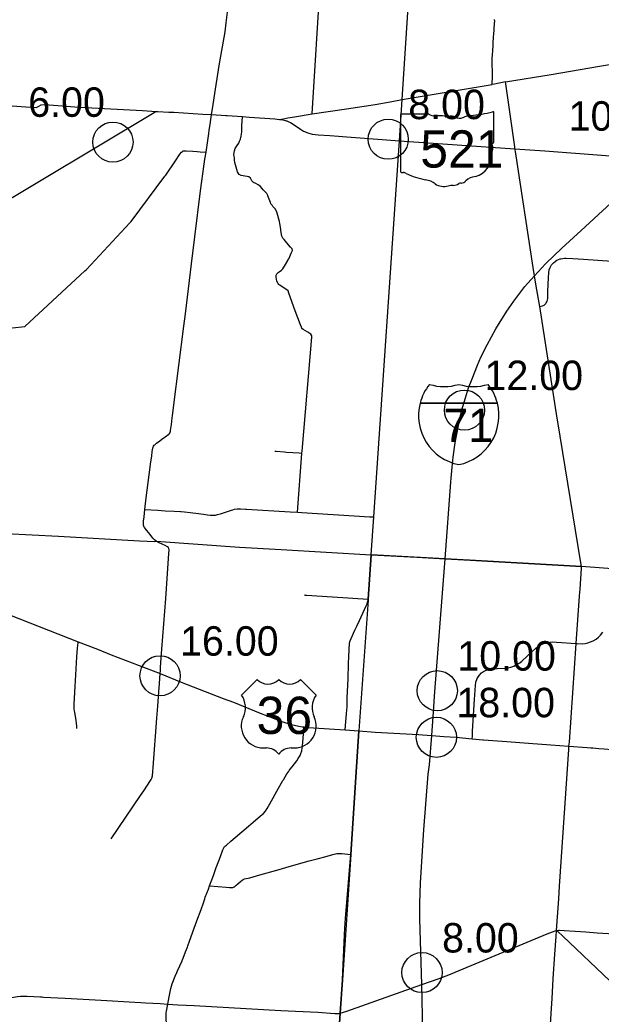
# Model space of a CAD drawing. Extents: x 1597222 to 1925846, y 496284 to 911751.
# Drawn here: x 1833850 to 1855559, y 815408 to 852560 of the extents above; entities that cross this region are included whole.
import ezdxf

# ---------------------------------------------------------------- set-up
doc = ezdxf.new("R2010")
doc.units = 0
for name, color, linetype in [('Default', 7, 'Continuous'), ('GM_X_County_Road', 7, 'Continuous'), ('GM_X_Interstate_Route', 7, 'Continuous'), ('GM_X_Interstate_Shield', 7, 'Continuous'), ('GM_X_State_Route', 7, 'Continuous'), ('GM_X_State_Shield', 7, 'Continuous'), ('GM_X_Township', 7, 'Continuous'), ('GM_X_Township_Road', 7, 'Continuous'), ('GM_X_US_Route', 7, 'Continuous'), ('GM_X_US_Shield', 7, 'Continuous')]:
    doc.layers.add(name, color=color, linetype=linetype)

msp = doc.modelspace()

# ---------------------------------------------------------------- linework, layer by layer
at = {"layer": 'Default'}
for centre in [(1837325, 847992), (1847607, 848101), (1850454, 837978), (1839084, 828052), (1849439, 827494), (1849405, 825751), (1848869, 816960)]:
    msp.add_circle(centre, 750, dxfattribs=at)
at = {"layer": 'GM_X_County_Road'}
for points in [[(1841006, 849018), (1841051, 849314), (1841101, 849645), (1841295, 850857), (1841512, 852119), (1841560, 852444), (1841625, 853051)], [(1852342, 847746), (1852332, 847819), (1852002, 850172), (1851992, 850242), (1851578, 850159), (1851485, 850140), (1851503, 850457), (1851507, 850519), (1851495, 850994), (1851492, 851085), (1851506, 851296), (1851510, 851368), (1851545, 851947), (1851548, 852007), (1851578, 852429), (1851584, 852517), (1851577, 852569)], [(1851992, 850242), (1853696, 850524), (1855503, 850836), (1856828, 851059), (1859214, 851472), (1860807, 851754), (1861908, 851967)], [(1848128, 849585), (1851485, 850140)], [(1828890, 849668), (1828890, 849668), (1828924, 849648), (1828977, 849643), (1829879, 849585), (1833037, 849389), (1834076, 849311), (1834469, 849288), (1834642, 849380), (1834781, 849392), (1836063, 849299), (1838431, 849174), (1838783, 849153), (1838998, 849141)], [(1843595, 848838), (1843637, 848852), (1843852, 848894), (1844102, 848937), (1844768, 849049), (1846050, 849232), (1847118, 849400), (1847685, 849497), (1848128, 849585)], [(1846971, 832575), (1846971, 832575), (1847065, 833986), (1848030, 848046), (1848128, 849585)], [(1838934, 833082), (1838875, 833130), (1838820, 833190), (1838713, 833324), (1838593, 833477), (1838502, 833596), (1838490, 833616), (1838481, 833634), (1838474, 833652), (1838468, 833671), (1838464, 833691), (1838461, 833711), (1838461, 833751), (1838466, 833825), (1838487, 833985), (1838519, 834265), (1838567, 834705), (1838674, 835560), (1838743, 836040), (1838773, 836253), (1838796, 836429), (1838814, 836551), (1838826, 836590), (1838844, 836629), (1838867, 836664), (1838885, 836685), (1838954, 836740), (1839072, 836824), (1839157, 836890), (1839273, 836974), (1839413, 837081), (1839426, 837095), (1839438, 837110), (1839458, 837143), (1839466, 837161), (1839472, 837179), (1839477, 837198), (1839478, 837221), (1839510, 837440), (1839538, 837684), (1839547, 837760), (1839596, 838176), (1839967, 841111), (1840035, 841581), (1840259, 843439), (1840381, 844450), (1840596, 846166), (1840736, 847171), (1840762, 847354), (1840807, 847615), (1840906, 848311), (1840922, 848444), (1840955, 848656), (1841006, 849018)], [(1833453, 841041), (1833926, 841092), (1834029, 841103), (1836280, 843180), (1836334, 843229), (1837952, 844970), (1838003, 845024), (1839263, 846719), (1839296, 846763), (1839657, 847296), (1839829, 847544), (1839890, 847618), (1839921, 847646), (1839949, 847661), (1839978, 847670), (1839994, 847672), (1840065, 847668), (1840312, 847648), (1840471, 847640), (1840580, 847631), (1840807, 847615)], [(1854821, 832136), (1854806, 832276), (1853927, 837618), (1853916, 837681), (1853270, 841855), (1853135, 842607), (1853071, 843001), (1853019, 843312), (1852359, 847640), (1852342, 847746)], [(1839405, 832831), (1839399, 832841), (1839368, 832866), (1839279, 832914), (1839055, 833020), (1838934, 833082)], [(1839090, 828131), (1839096, 828247), (1839106, 828377), (1839155, 829045), (1839297, 830940), (1839419, 832616), (1839427, 832761), (1839419, 832807), (1839405, 832831)], [(1846005, 826026), (1846043, 826645), (1846071, 826890), (1846074, 827230), (1846113, 827938), (1846126, 828505), (1846142, 828753), (1846166, 829288), (1846184, 829357), (1846219, 829446), (1846366, 829753), (1846439, 829908), (1846529, 830116), (1846779, 830659), (1846815, 830740), (1846834, 830797), (1846854, 830870), (1846863, 830918), (1846971, 832575)], [(1854753, 831025), (1854754, 831032), (1854771, 831285), (1854824, 832063), (1854821, 832136)], [(1854354, 825422), (1854377, 825574), (1854631, 829258), (1854753, 831025)], [(1850745, 825700), (1850750, 825794), (1850761, 825975), (1850834, 827165), (1850866, 827684), (1850884, 827817), (1850934, 827955), (1851000, 828061), (1851089, 828156), (1851167, 828213), (1851241, 828254), (1851342, 828291), (1851425, 828309), (1851528, 828316), (1851677, 828322), (1851998, 828336), (1852079, 828347), (1852187, 828372), (1852301, 828412), (1852366, 828442), (1852454, 828491), (1852522, 828537), (1852593, 828595), (1852985, 828961), (1853110, 829075), (1853198, 829141), (1853285, 829192), (1853384, 829239), (1853471, 829269), (1853550, 829290), (1853650, 829307), (1853759, 829315), (1853892, 829310), (1854631, 829258)], [(1837255, 821964), (1838352, 823573), (1838477, 823753), (1838734, 824138), (1838754, 824176), (1838776, 824230), (1838797, 824315), (1838813, 824478), (1838822, 824624), (1838961, 826468), (1838996, 826913), (1839038, 827452), (1839065, 827768), (1839090, 828131)], [(1844428, 825666), (1844430, 825701), (1844439, 825894), (1844455, 826141)], [(1843676, 824135), (1843691, 824163), (1843825, 824382), (1843877, 824459), (1843910, 824506), (1843948, 824557), (1844017, 824645), (1844192, 824870), (1844248, 824955), (1844313, 825075), (1844345, 825149), (1844376, 825251), (1844395, 825340), (1844404, 825395), (1844424, 825605), (1844428, 825666)], [(1853892, 818538), (1853927, 819045), (1853979, 819713), (1854011, 820193), (1854357, 825298), (1854354, 825422)], [(1840108, 817915), (1840125, 817960), (1840185, 818129), (1840360, 818619), (1840456, 818888), (1840615, 819321), (1840707, 819568), (1840763, 819722), (1840773, 819774), (1840889, 820072), (1840934, 820196), (1841077, 820583), (1841186, 820882), (1841282, 821134), (1841343, 821301), (1841435, 821553), (1841459, 821602), (1841482, 821642), (1841498, 821666), (1841562, 821727), (1841728, 821872), (1841885, 822009), (1842387, 822426), (1842567, 822583), (1842842, 822816), (1842945, 822908), (1843026, 822996), (1843091, 823097), (1843134, 823175), (1843183, 823260), (1843512, 823845), (1843676, 824135)], [(1845813, 815443), (1846057, 815523), (1847704, 816100), (1848860, 816509), (1849512, 816739), (1849867, 816870), (1850255, 817032), (1853548, 818404), (1853845, 818524), (1853892, 818538)], [(1852972, 804706), (1852981, 804856), (1853110, 806745), (1853175, 807697), (1853246, 808714), (1853530, 812876), (1853592, 813742), (1853681, 815234), (1853705, 815613), (1853731, 815995), (1853772, 816725), (1853832, 817646), (1853875, 818312), (1853892, 818538)], [(1853892, 818538), (1853963, 818545), (1854011, 818543), (1854178, 818529), (1854595, 818503), (1854991, 818481), (1855415, 818448), (1856692, 818365)], [(1857182, 815299), (1857153, 815378), (1857124, 815436), (1857089, 815491), (1857039, 815553), (1856865, 815727), (1856650, 815933), (1856316, 816250), (1855886, 816655), (1854135, 818318), (1853948, 818496), (1853892, 818538)], [(1839372, 815780), (1839425, 816059), (1839488, 816370), (1839533, 816537), (1839646, 816828), (1839707, 816968), (1839735, 817030), (1839908, 817404), (1839909, 817406), (1839949, 817498), (1840041, 817739), (1840108, 817915)], [(1831958, 816015), (1832323, 815989), (1832460, 815979), (1832837, 815953), (1832930, 815950), (1833024, 815953), (1833112, 815962), (1833413, 816008), (1833762, 816064), (1833870, 816076), (1833979, 816082), (1834125, 816080), (1834617, 816051), (1834676, 816048), (1834735, 816046), (1835535, 816000), (1836888, 815933), (1838141, 815859), (1838366, 815848), (1838544, 815828), (1839093, 815806), (1839372, 815780)], [(1842846, 805301), (1842837, 805328), (1842772, 805518), (1842519, 806229), (1841146, 810217), (1840928, 810827), (1840065, 813066), (1839518, 814468), (1839479, 814577), (1839387, 814825), (1839342, 814985), (1839324, 815084), (1839310, 815214), (1839307, 815315), (1839311, 815371), (1839312, 815408), (1839319, 815463), (1839325, 815513), (1839372, 815780)], [(1839372, 815780), (1839750, 815761), (1840057, 815746), (1840358, 815730), (1843594, 815549), (1844974, 815476), (1845607, 815434), (1845771, 815433), (1845813, 815443)]]:
    msp.add_lwpolyline(points, dxfattribs=at)
at = {"layer": 'GM_X_Interstate_Route'}
for points in [[(1853497, 843457), (1854091, 844035), (1854810, 844689), (1856408, 846161), (1857196, 846884), (1857351, 847028)], [(1852825, 842723), (1853071, 843001), (1853486, 843445), (1853497, 843457)], [(1849960, 835440), (1849991, 835852), (1850027, 836225), (1850112, 836751), (1850219, 837345), (1850270, 837606), (1850358, 837993), (1850490, 838443), (1850609, 838810), (1850743, 839153), (1850946, 839662), (1851071, 839958), (1851303, 840416), (1851627, 841020), (1852032, 841680), (1852294, 842043), (1852715, 842598), (1852825, 842723)], [(1849232, 825823), (1849312, 826884), (1849342, 827283), (1849536, 829857), (1849737, 832422), (1849949, 835289), (1849960, 835440)], [(1848894, 814749), (1848860, 816509), (1848794, 818972), (1848791, 819542), (1848815, 820309), (1848943, 822290), (1849103, 824378), (1849147, 824725), (1849232, 825823)]]:
    msp.add_lwpolyline(points, dxfattribs=at)
at = {"layer": 'GM_X_Interstate_Shield'}
for p, q in [((1848799, 838237), (1851684, 838237)), ((1851684, 838237), (1848799, 838237)), ((1851684, 838237), (1848799, 838237)), ((1848799, 838237), (1851684, 838237)), ((1851684, 838237), (1848799, 838237)), ((1851684, 838237), (1848799, 838237))]:
    msp.add_line(p, q, dxfattribs=at)
for centre, start, end in [((1850616, 837777), 141.669, 165.8066), ((1850616, 837777), 141.669, 165.8066), ((1849693, 840733), 253.0091, 286.9909), ((1849693, 840733), 253.0091, 286.9909), ((1850789, 840733), 253.0091, 286.9909), ((1850789, 840733), 253.0091, 286.9909), ((1849866, 837777), 14.1934, 38.331), ((1849866, 837777), 14.1934, 38.331), ((1850616, 837777), 165.8066, 258.463), ((1850616, 837777), 165.8066, 258.463), ((1849866, 837777), 281.537, 14.1934), ((1849866, 837777), 281.537, 14.1934)]:
    msp.add_arc(centre, 1875, start, end, dxfattribs=at)
at = {"layer": 'GM_X_State_Route'}
for points in [[(1824240, 840319), (1825270, 840939), (1826096, 841440), (1826142, 841474), (1826514, 841694), (1827976, 842576), (1829017, 843200), (1831719, 844816), (1832490, 845282), (1838868, 849097), (1838914, 849121), (1838998, 849141), (1839418, 849116)], [(1839418, 849116), (1839597, 849106), (1840678, 849037), (1841006, 849018)], [(1841006, 849018), (1841537, 848985), (1841586, 848982)], [(1841586, 848982), (1842167, 848948), (1842431, 848928)], [(1842431, 848928), (1843370, 848858), (1843543, 848843)], [(1843543, 848843), (1843595, 848838), (1843668, 848826), (1843754, 848804), (1843796, 848791), (1843824, 848782), (1843899, 848751), (1843959, 848721), (1844210, 848561), (1844336, 848473), (1844448, 848406), (1844608, 848336), (1844771, 848292), (1844988, 848267), (1845431, 848234), (1846221, 848181), (1847382, 848093), (1848030, 848046), (1852342, 847746), (1853462, 847664), (1857695, 847346)]]:
    msp.add_lwpolyline(points, dxfattribs=at)
at = {"layer": 'GM_X_State_Shield'}
for p, q in [((1848068, 849005), (1848068, 846891)), ((1848068, 849005), (1848068, 846891)), ((1849122, 849041), (1848102, 849041)), ((1849122, 849041), (1848102, 849041)), ((1851549, 847988), (1851549, 849093)), ((1851549, 847988), (1851549, 849093)), ((1851548, 847988), (1851549, 847988)), ((1851548, 847988), (1851549, 847988))]:
    msp.add_line(p, q, dxfattribs=at)
for centre, major_axis, start_param, end_param in [((1848108, 849009), (40.3, 0), 1.712693, 3.28349), ((1848108, 849009), (40.3, 0), 1.712693, 3.28349), ((1849364, 849286), (391, 0), 4.042523, 4.731795), ((1849364, 849286), (391, 0), 4.042523, 4.731795), ((1849494, 847855), (1404, 0), 1.404758, 1.657858), ((1849494, 847855), (1404, 0), 1.404758, 1.657858), ((1849813, 849020), (113, 0), 3.836095, 5.185415), ((1849813, 849020), (113, 0), 3.836095, 5.185415), ((1849978, 848776), (235, 0), 0.950623, 2.079405), ((1849978, 848776), (235, 0), 0.950623, 2.079405), ((1850281, 849111), (282, 0), 4.081561, 5.145723), ((1850281, 849111), (282, 0), 4.081561, 5.145723), ((1850780, 848395), (743, 0), 1.699011, 2.107814), ((1850780, 848395), (743, 0), 1.699011, 2.107814), ((1850309, 851922), (3691, 0), 4.814394, 5.042369), ((1850309, 851922), (3691, 0), 4.814394, 5.042369), ((1851510, 849098), (38.7, 0), 6.141152, 7.989035), ((1851510, 849098), (38.7, 0), 6.141152, 7.989035), ((1851540, 847907), (60, 0), 1.883978, 3.671073), ((1851540, 847907), (60, 0), 1.883978, 3.671073), ((1851158, 847767), (360, 0), 5.934695, 6.695948), ((1851158, 847767), (360, 0), 5.934695, 6.695948), ((1851507, 847984), (41.5, 0), 5.05454, 6.418171), ((1851507, 847984), (41.5, 0), 5.05454, 6.418171), ((1850515, 847385), (923, 0), 5.101752, 6.440018), ((1850515, 847385), (923, 0), 5.101752, 6.440018), ((1851687, 847525), (262, 0), 2.387724, 3.262537), ((1851687, 847525), (262, 0), 2.387724, 3.262537), ((1848108, 846887), (40.7, 0), 3.00124, 4.508301), ((1848108, 846887), (40.7, 0), 3.00124, 4.508301), ((1848115, 847103), (310, 0), 4.665946, 4.897461), ((1848115, 847103), (310, 0), 4.665946, 4.897461), ((1848178, 846769), (112, 0), 0.519207, 1.627899), ((1848178, 846769), (112, 0), 0.519207, 1.627899), ((1849591, 848668), (2665, 0), 4.195997, 4.488961), ((1849591, 848668), (2665, 0), 4.195997, 4.488961), ((1850905, 846298), (506, 0), 1.647645, 2.488434), ((1850905, 846298), (506, 0), 1.647645, 2.488434), ((1848797, 845942), (834, 0), 0.823519, 1.323587), ((1848797, 845942), (834, 0), 0.823519, 1.323587), ((1849699, 846759), (529, 0), 4.026481, 4.996735), ((1849699, 846759), (529, 0), 4.026481, 4.996735), ((1850004, 846028), (435, 0), 1.495662, 1.94098), ((1850004, 846028), (435, 0), 1.495662, 1.94098), ((1850043, 846601), (282, 0), 4.691044, 5.507374), ((1850043, 846601), (282, 0), 4.691044, 5.507374), ((1850298, 846396), (79.4, 0), 1.147584, 2.315152), ((1850298, 846396), (79.4, 0), 1.147584, 2.315152), ((1850264, 846686), (298, 0), 4.937069, 5.64225), ((1850264, 846686), (298, 0), 4.937069, 5.64225)]:
    msp.add_ellipse(centre, major_axis=major_axis, ratio=0.8, start_param=start_param, end_param=end_param, dxfattribs=at)
at = {"layer": 'GM_X_Township'}
for points in [[(1858606, 831851), (1854821, 832136), (1851310, 832334), (1849737, 832422), (1846971, 832575), (1847065, 833986), (1848030, 848046), (1848128, 849585), (1848752, 859146), (1850615, 859080), (1861827, 858324)], [(1832327, 833414), (1835297, 833263), (1838313, 833094), (1838887, 833066), (1838934, 833082), (1842052, 832856), (1843609, 832772), (1846971, 832575), (1846863, 830918), (1846854, 830870), (1846509, 825988), (1846205, 821378), (1845900, 816686), (1845813, 815443), (1845687, 813540)]]:
    msp.add_lwpolyline(points, dxfattribs=at)
at = {"layer": 'GM_X_Township_Road'}
for points in [[(1844768, 849049), (1845076, 854067), (1843711, 854157), (1843711, 854157)], [(1843111, 845983), (1843107, 845993), (1843076, 846068), (1843002, 846144), (1842938, 846209), (1842834, 846328), (1842792, 846377), (1842745, 846400), (1842658, 846443), (1842580, 846479), (1842518, 846549), (1842493, 846596), (1842466, 846646), (1842396, 846696), (1842344, 846704), (1842246, 846720), (1842194, 846729), (1842110, 846744), (1842034, 846776), (1842009, 846822), (1841976, 846884), (1841907, 847139), (1841882, 847229), (1841869, 847334), (1841860, 847401), (1841852, 847454), (1841840, 847528), (1841863, 847661), (1841896, 847749), (1841968, 847865), (1842022, 847959), (1842058, 848032), (1842084, 848101), (1842105, 848172), (1842112, 848208), (1842126, 848296), (1842134, 848374), (1842137, 848623), (1842150, 848766), (1842167, 848948)], [(1843823, 844224), (1843717, 844351), (1843674, 844402), (1843630, 844475), (1843602, 844684), (1843594, 844739), (1843558, 844947), (1843544, 845028), (1843460, 845334), (1843438, 845415), (1843386, 845501), (1843361, 845526), (1843349, 845538), (1843298, 845589), (1843268, 845633), (1843228, 845691), (1843209, 845741), (1843188, 845798), (1843111, 845983)], [(1843771, 843420), (1843860, 843570), (1843863, 843575), (1843892, 843625), (1843997, 843867), (1844030, 843945), (1844022, 844005), (1843954, 844068), (1843823, 844224)], [(1843677, 842566), (1843609, 842613), (1843559, 842648), (1843513, 842674), (1843503, 842690), (1843491, 842712), (1843453, 842794), (1843429, 842865), (1843423, 842949), (1843423, 843023), (1843441, 843067), (1843499, 843117), (1843540, 843150), (1843617, 843209), (1843675, 843258), (1843771, 843420)], [(1853270, 841855), (1853375, 841876), (1853430, 841904), (1853489, 841960), (1853510, 841987), (1853529, 842020), (1853540, 842047), (1853556, 842102), (1853564, 842152), (1853571, 842416), (1853597, 842931), (1853607, 843104), (1853625, 843215), (1853660, 843313), (1853709, 843404), (1853779, 843484), (1853838, 843531), (1853844, 843535)], [(1853844, 843535), (1853861, 843548), (1853911, 843579), (1853965, 843605), (1854028, 843627), (1854060, 843636), (1854125, 843648), (1854191, 843655), (1854258, 843655), (1854503, 843639), (1854896, 843613), (1855969, 843548)], [(1844215, 834160), (1844384, 836360), (1844385, 836371), (1844391, 836449), (1844748, 840708), (1844751, 840754), (1844719, 840820), (1844674, 840847), (1844607, 840886), (1844427, 840996), (1844381, 841024), (1844362, 841073), (1844329, 841160), (1844136, 841693), (1843898, 842352), (1843869, 842432), (1843677, 842566)], [(1843367, 836442), (1843417, 836439), (1843733, 836416), (1843809, 836411), (1844283, 836378), (1844385, 836371)], [(1838519, 834265), (1839003, 834239), (1839280, 834220), (1839610, 834202), (1839845, 834186), (1839872, 834185)], [(1839872, 834185), (1840004, 834176), (1840213, 834155), (1840314, 834142), (1840419, 834128), (1840709, 834086), (1840854, 834066), (1840955, 834057), (1841058, 834052), (1841152, 834058), (1841236, 834072), (1841340, 834101), (1841488, 834149), (1841639, 834205), (1841751, 834242), (1841801, 834256), (1841870, 834271), (1841962, 834284), (1842018, 834287), (1842093, 834287), (1842280, 834278)], [(1842280, 834278), (1842320, 834277), (1843950, 834176), (1844215, 834160), (1844383, 834149), (1846926, 833987), (1847065, 833986)], [(1832327, 833414), (1835297, 833263), (1838313, 833094), (1838887, 833066), (1838934, 833082)], [(1846971, 832575), (1848673, 832481)], [(1848673, 832481), (1849737, 832422), (1850671, 832370)], [(1850671, 832370), (1851310, 832334), (1854821, 832136)], [(1844480, 831093), (1844497, 831060), (1844550, 831060), (1845524, 831004), (1846863, 830918)], [(1854631, 829258), (1854661, 829256), (1854846, 829249), (1854959, 829261), (1855061, 829283), (1855161, 829315), (1855264, 829362), (1855369, 829424), (1855456, 829490), (1855539, 829573), (1855621, 829675)], [(1835977, 826077), (1835975, 826171), (1835970, 826275), (1835952, 826385), (1835926, 826541), (1835897, 826684), (1835886, 826742), (1835877, 826818), (1835875, 826895), (1835879, 826972), (1835915, 827662), (1835926, 827862), (1835981, 828758), (1836002, 829086), (1836021, 829286), (1836024, 829315)], [(1846205, 821378), (1846509, 825988)], [(1840934, 820196), (1841554, 820152), (1841675, 820144), (1841771, 820139), (1841789, 820141), (1841806, 820145), (1841824, 820150), (1841857, 820165), (1841886, 820186), (1841932, 820222), (1841987, 820273), (1842088, 820362), (1842150, 820411), (1842188, 820437), (1842243, 820457), (1842436, 820506), (1842558, 820533), (1842815, 820608), (1843441, 820786), (1843996, 820944), (1844660, 821131), (1844951, 821209), (1845239, 821285), (1845542, 821368), (1845693, 821404), (1845774, 821406), (1845873, 821404), (1846205, 821378)], [(1845813, 815443), (1845900, 816686), (1845973, 818365), (1845978, 818443), (1845984, 818548), (1845988, 818619), (1846010, 818988), (1846205, 821378)], [(1845336, 808240), (1845452, 810003), (1845637, 812811), (1845670, 813309), (1845687, 813540), (1845813, 815443)]]:
    msp.add_lwpolyline(points, dxfattribs=at)
at = {"layer": 'GM_X_US_Route'}
for points in [[(1833463, 830322), (1836024, 829315), (1836751, 829041), (1837258, 828837), (1838300, 828432), (1839090, 828131), (1839877, 827816), (1841448, 827196), (1841834, 827061), (1842819, 826655), (1843343, 826451), (1843520, 826379), (1843742, 826300), (1843999, 826225), (1844265, 826170), (1844402, 826149)], [(1844402, 826149), (1844455, 826141), (1844585, 826124), (1844623, 826121), (1846005, 826026), (1846509, 825988)], [(1846509, 825988), (1847116, 825949), (1848742, 825856), (1848890, 825849), (1849232, 825823)], [(1849232, 825823), (1849538, 825792), (1849689, 825784)], [(1849689, 825784), (1850151, 825758), (1850745, 825700), (1851142, 825661), (1851169, 825659)], [(1851169, 825659), (1852041, 825594), (1852847, 825534), (1853684, 825470), (1854354, 825422), (1855037, 825370)], [(1855037, 825370), (1855173, 825360), (1855248, 825354), (1855476, 825337), (1855674, 825320), (1855808, 825306), (1855988, 825281), (1856219, 825240), (1856454, 825186), (1856610, 825146), (1856879, 825067), (1857093, 824992), (1857448, 824848), (1857746, 824717), (1857872, 824661)]]:
    msp.add_lwpolyline(points, dxfattribs=at)
at = {"layer": 'GM_X_US_Shield'}
for p, q in [((1842708, 827907), (1842128, 827327)), ((1842708, 827907), (1842128, 827327)), ((1844912, 827327), (1844332, 827907)), ((1844912, 827327), (1844332, 827907)), ((1842940, 825355), (1843056, 825355)), ((1842940, 825355), (1843056, 825355)), ((1843984, 825355), (1844100, 825355)), ((1843984, 825355), (1844100, 825355))]:
    msp.add_line(p, q, dxfattribs=at)
for centre, radius, start, end in [((1843114, 828322), 580, 225.573, 314.427), ((1843114, 828322), 580, 225.573, 314.427), ((1843926, 828322), 580, 225.573, 314.427), ((1843926, 828322), 580, 225.573, 314.427), ((1841463, 826861), 812, 334.5471, 35.0009), ((1841463, 826861), 812, 334.5471, 35.0009), ((1845578, 826861), 812, 144.9991, 205.4529), ((1845578, 826861), 812, 144.9991, 205.4529), ((1842931, 826167), 812, 154.8319, 270.6383), ((1842931, 826167), 812, 154.8319, 270.6383), ((1844109, 826167), 812, 269.3617, 25.1681), ((1844109, 826167), 812, 269.3617, 25.1681), ((1843056, 824775), 580, 36.8699, 90), ((1843056, 824775), 580, 36.8699, 90), ((1843984, 824775), 580, 90, 143.1301), ((1843984, 824775), 580, 90, 143.1301)]:
    msp.add_arc(centre, radius, start, end, dxfattribs=at)

# ---------------------------------------------------------------- texts
at = {"layer": 'Default'}
for s, p in [('6.00', (1834161, 848937)), ('8.00', (1848357, 848851)), ('10.00', (1854346, 848420)), ('12.00', (1851204, 838728)), ('16.00', (1839834, 828802)), ('10.00', (1850189, 828244)), ('18.00', (1850155, 826501)), ('8.00', (1849619, 817710))]:
    msp.add_text(s, height=1100, dxfattribs=at).set_placement(p)
at = {"layer": 'GM_X_Interstate_Shield'}
msp.add_text('71', height=1250, dxfattribs=at).set_placement((1849664, 836784))
msp.add_text('71', height=1250, dxfattribs=at).set_placement((1849664, 836784))
at = {"layer": 'GM_X_State_Shield'}
msp.add_text('521', height=1392.2, dxfattribs=at).set_placement((1848805, 847040))
msp.add_text('521', height=1392.2, dxfattribs=at).set_placement((1848805, 847040))
at = {"layer": 'GM_X_US_Shield'}
msp.add_text('36', height=1392.2, dxfattribs=at).set_placement((1842693, 825877))
msp.add_text('36', height=1392.2, dxfattribs=at).set_placement((1842693, 825877))

doc.saveas('drawing.dxf')
